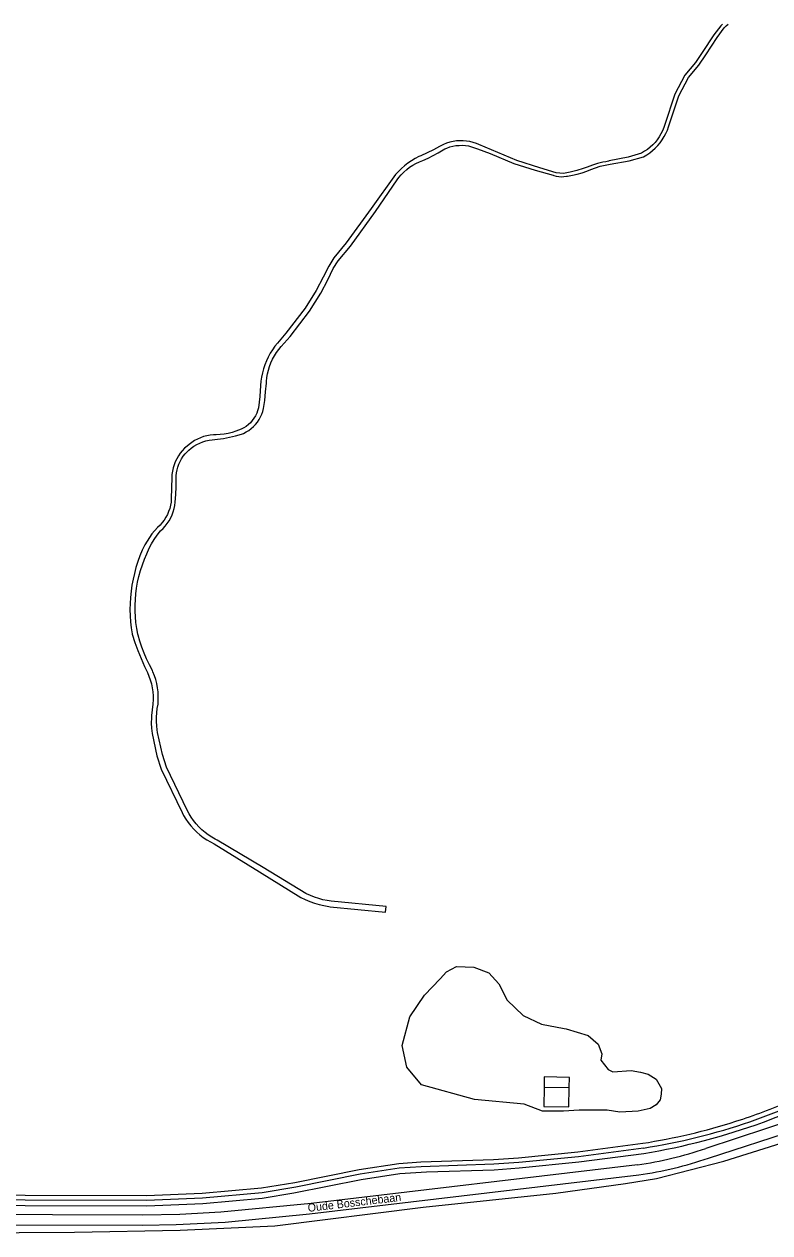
# Model space of a CAD drawing. Extents: x 137000 to 140001, y 403500 to 406000.
# Drawn here: x 138682.6 to 138915.5, y 405622.5 to 406000 of the extents above; entities that cross this region are included whole.
import ezdxf

# ---------------------------------------------------------------- set-up
doc = ezdxf.new("R2010")
doc.units = 0
for name, color, linetype in [('gg-anno-openbare ruimte label', 7, 'Continuous'), ('gg-bbg-luifel en loopbrug', 7, 'Continuous'), ('gg-bbg-overig bouwwerk', 7, 'Continuous'), ('gg-knt-bronhoudergrens', 7, 'Continuous'), ('gg-knt-verharding', 7, 'Continuous'), ('gt-grn-groengrens', 7, 'Continuous'), ('gt-grn-groengrens NZ', 7, 'Continuous'), ('gx-grn-maaiveld', 7, 'Continuous')]:
    doc.layers.add(name, color=color, linetype=linetype)

msp = doc.modelspace()

# ---------------------------------------------------------------- linework, layer by layer
at = {"layer": 'gg-bbg-luifel en loopbrug'}
msp.add_line((138845.02, 405668.06), (138852.87, 405667.93), dxfattribs=at)
msp.add_lwpolyline([(138852.87, 405667.93), (138852.92, 405671.08), (138845.08, 405671.21), (138845.02, 405668.06)], dxfattribs=at)
at = {"layer": 'gg-bbg-overig bouwwerk'}
msp.add_lwpolyline([(138845.02, 405668.06), (138844.92, 405662.04), (138852.76, 405661.91), (138852.87, 405667.93)], dxfattribs=at)
at = {"layer": 'gg-knt-bronhoudergrens'}
msp.add_lwpolyline([(138659.36, 405622.56), (138663.63, 405622.55), (138698.36, 405622.75), (138731.28, 405623.33), (138760.93, 405624.73), (138807.2, 405630.57), (138848.69, 405634.92), (138870.43, 405637.95), (138880.17, 405639.47), (138901.12, 405644.91), (138929.96, 405653.95), (138949.6, 405660.12), (138957.13, 405662.06), (138962.26, 405662.86), (138977.74, 405662.68)], dxfattribs=at)
at = {"layer": 'gg-knt-verharding'}
for p, q in [((138943.08, 405664.55), (138895.49, 405648.85)), ((138896.38, 405645.88), (138943.82, 405661.31))]:
    msp.add_line(p, q, dxfattribs=at)
for points in [[(138913.57, 405657.13), (138917.53, 405658.62), (138921.47, 405660.18), (138924.88, 405661.61), (138928.27, 405663.1), (138933.91, 405665.95)], [(138606.79, 405631.24), (138720.86, 405630.99), (138738.44, 405631.71), (138756.93, 405633.38), (138766.88, 405635.02), (138787.84, 405639.17), (138799.96, 405641.1), (138808.28, 405641.59), (138829.37, 405642.26), (138837.25, 405642.82), (138855.9, 405644.69), (138876.13, 405647.31)], [(138876.03, 405649.02), (138855.75, 405646.31), (138837.13, 405644.49), (138829.28, 405643.99), (138806.56, 405643.19), (138799.78, 405642.75), (138787.55, 405640.82), (138767.44, 405636.82), (138756.97, 405635.08), (138738.33, 405633.38), (138720.82, 405632.69), (138606.85, 405632.97)], [(138874.22, 405643.73), (138772.25, 405631.7), (138744, 405628.98), (138731.23, 405628.29), (138719.7, 405628.09), (138606.68, 405628.5)], [(138606.6, 405625.15), (138719.6, 405624.93), (138730.03, 405625.11), (138745.36, 405625.88), (138771.74, 405628.49), (138874.58, 405640.63)]]:
    msp.add_lwpolyline(points, dxfattribs=at)
for centre, radius, start, end in [((138846.5, 405839.73), 192.99, 288.9912, 293.1914), ((138846.57, 405839.6), 192.84, 278.7876, 288.984), ((138841.4, 405855.99), 211.55, 279.449, 289.9462), ((138853.13, 405778.11), 136.02, 278.9209, 288.1439), ((138857.67, 405758.77), 119.34, 278.1474, 288.9272)]:
    msp.add_arc(centre, radius, start, end, dxfattribs=at)
at = {"layer": 'gt-grn-groengrens'}
msp.add_lwpolyline([(138803.04, 405689.95), (138807.65, 405696.78), (138812.54, 405701.82), (138814.56, 405704.01), (138817.61, 405705.73), (138823.09, 405705.48), (138827.76, 405703.77), (138830.89, 405700.34), (138833.49, 405695.18), (138838.49, 405690.42), (138844.19, 405687.68), (138851.23, 405686.33), (138851.91, 405686.2), (138858.74, 405684.21), (138861.87, 405681.43), (138863.07, 405678.42), (138862.78, 405676.46), (138864.98, 405673.59), (138866.52, 405672.79), (138872.23, 405673.23), (138875.13, 405672.75), (138877.56, 405672.09), (138880.04, 405670.53), (138881.72, 405667.62), (138881.62, 405665.84), (138881.28, 405664.11), (138880.01, 405662.47), (138878.18, 405661.4), (138874.43, 405660.57), (138868.68, 405660.27), (138864.7, 405660.89), (138855.94, 405660.88), (138851.12, 405660.57), (138844.47, 405660.5), (138838.77, 405662.77), (138823.32, 405664.14), (138806.67, 405668.8), (138802.15, 405674.3), (138800.67, 405681.05), (138803.04, 405689.95)], dxfattribs=at)
for centre, radius, start, end in [((138846.4, 405840), 191.77, 287.7607, 293.1874), ((138846.54, 405839.73), 191.47, 278.7943, 287.7443)]:
    msp.add_arc(centre, radius, start, end, dxfattribs=at)
at = {"layer": 'gt-grn-groengrens NZ'}
msp.add_lwpolyline([(138606.84, 405634.47), (138720.79, 405634.19), (138738.23, 405634.88), (138756.78, 405636.57), (138767.17, 405638.3), (138787.29, 405642.3), (138799.62, 405644.24), (138806.49, 405644.69), (138829.21, 405645.49), (138837.01, 405645.99), (138855.58, 405647.8), (138875.82, 405650.51)], dxfattribs=at)
at = {"layer": 'gx-grn-maaiveld'}
msp.add_lwpolyline([(138900.74, 406000), (138900.2, 405999.46), (138898.02, 405996.68), (138894.42, 405991.2), (138892.3, 405987.99), (138888.99, 405984.1), (138885.9, 405978.11), (138882.61, 405968.34), (138882.4, 405967.71), (138881.99, 405966.71), (138881.52, 405965.74), (138880.97, 405964.81), (138880.36, 405963.93), (138879.68, 405963.09), (138878.95, 405962.3), (138878.15, 405961.57), (138877.31, 405960.9), (138876.42, 405960.29), (138875.48, 405959.76), (138871.28, 405958.45), (138865.31, 405957.27), (138865.09, 405957.23), (138864.25, 405957.06), (138863.41, 405956.89), (138861.74, 405956.46), (138860.1, 405955.96), (138858.49, 405955.39), (138857.2, 405954.95), (138855.19, 405954.33), (138853.16, 405953.79), (138851.11, 405953.32), (138849.95, 405953.46), (138848.78, 405953.6), (138843.65, 405955.16), (138836.54, 405957.44), (138824.65, 405962.46), (138823.88, 405962.77), (138822.87, 405963.09), (138821.84, 405963.34), (138820.79, 405963.51), (138819.74, 405963.6), (138818.68, 405963.6), (138817.62, 405963.53), (138816.57, 405963.38), (138815.54, 405963.15), (138814.53, 405962.85), (138813.54, 405962.46), (138812.3, 405961.75), (138810.41, 405960.73), (138808.48, 405959.78), (138806.52, 405958.91), (138805.91, 405958.63), (138804.73, 405958.03), (138803.58, 405957.36), (138802.48, 405956.62), (138801.43, 405955.81), (138800.43, 405954.95), (138799.48, 405954.02), (138798.59, 405953.04), (138791.04, 405942.42), (138783.23, 405931.69), (138779.32, 405927.01), (138777.72, 405924.46), (138775.98, 405920.95), (138773.85, 405916.83), (138770.35, 405911.29), (138764.37, 405903.5), (138761.68, 405900.39), (138760.91, 405899.43), (138760.14, 405898.35), (138759.43, 405897.22), (138758.8, 405896.06), (138758.24, 405894.86), (138757.75, 405893.63), (138757.33, 405892.37), (138756.99, 405891.09), (138756.74, 405889.79), (138756.55, 405888.47), (138756.45, 405887.15), (138756.16, 405883.7), (138755.79, 405880.22), (138755.77, 405880.15), (138755.53, 405879.29), (138755.22, 405878.47), (138754.83, 405877.67), (138754.37, 405876.92), (138753.85, 405876.21), (138753.26, 405875.55), (138752.62, 405874.94), (138751.92, 405874.4), (138751.18, 405873.92), (138750.4, 405873.51), (138749.58, 405873.17), (138748.74, 405872.91), (138747.54, 405872.53), (138746.31, 405872.22), (138745.07, 405872), (138743.82, 405871.85), (138742.56, 405871.79), (138741.73, 405871.79), (138740.69, 405871.67), (138739.66, 405871.48), (138738.65, 405871.21), (138737.67, 405870.86), (138736.71, 405870.43), (138735.8, 405869.94), (138734.92, 405869.38), (138734.08, 405868.75), (138733.47, 405868.22), (138732.71, 405867.54), (138731.99, 405866.8), (138731.34, 405866), (138730.76, 405865.16), (138730.24, 405864.28), (138729.79, 405863.36), (138729.41, 405862.4), (138729.11, 405861.42), (138728.89, 405860.42), (138728.74, 405859.4), (138728.69, 405858.56), (138728.55, 405851.77), (138728.46, 405850.76), (138728.29, 405849.77), (138728.05, 405848.79), (138727.72, 405847.83), (138727.32, 405846.9), (138726.85, 405846.01), (138726.31, 405845.15), (138725.7, 405844.34), (138725.03, 405843.59), (138724.27, 405842.86), (138722.5, 405840.85), (138720.29, 405837.43), (138719.48, 405835.7), (138718.75, 405833.94), (138718.1, 405832.15), (138717.52, 405830.34), (138717.01, 405828.5), (138716.59, 405826.64), (138716.24, 405824.77), (138715.97, 405822.88), (138715.78, 405820.99), (138715.67, 405819.08), (138715.64, 405817.18), (138715.69, 405815.27), (138715.82, 405813.37), (138716.03, 405811.48), (138716.32, 405809.6), (138716.34, 405809.49), (138717.2, 405806.94), (138718.13, 405804.41), (138719.13, 405801.91), (138720.21, 405799.45), (138721.09, 405797.58), (138721.57, 405796.42), (138721.98, 405795.22), (138722.32, 405794), (138722.58, 405792.76), (138722.75, 405791.51), (138722.85, 405790.25), (138722.87, 405788.99), (138722.81, 405787.73), (138722.8, 405787.66), (138722.34, 405784.12), (138722.32, 405783.39), (138722.31, 405781.74), (138722.39, 405780.1), (138722.55, 405778.46), (138724.07, 405771.52), (138725.37, 405767.32), (138731.9, 405753.78), (138732.39, 405752.88), (138733.08, 405751.75), (138733.84, 405750.67), (138734.67, 405749.63), (138735.55, 405748.65), (138736.5, 405747.72), (138737.49, 405746.84), (138738.54, 405746.03), (138739.64, 405745.29), (138740.77, 405744.61), (138741.95, 405744.01), (138756.11, 405735.3), (138768.99, 405727.29), (138770.38, 405726.63), (138771.8, 405726.04), (138773.26, 405725.53), (138774.73, 405725.09), (138776.23, 405724.73), (138777.74, 405724.45), (138778.22, 405724.38), (138795.48, 405722.73), (138795.67, 405724.5), (138778.54, 405726.12), (138777.21, 405726.31), (138775.89, 405726.58), (138774.59, 405726.92), (138773.3, 405727.34), (138772.05, 405727.84), (138770.83, 405728.4), (138770.56, 405728.54), (138757.22, 405736.63), (138742.85, 405745.18), (138742.29, 405745.47), (138741.17, 405746.11), (138740.1, 405746.82), (138739.08, 405747.59), (138738.1, 405748.43), (138737.18, 405749.32), (138736.32, 405750.27), (138735.52, 405751.28), (138734.78, 405752.33), (138734.11, 405753.42), (138733.5, 405754.56), (138727.03, 405767.97), (138725.79, 405771.97), (138724.29, 405778.84), (138724.17, 405779.58), (138724.01, 405780.92), (138723.93, 405782.27), (138723.93, 405783.62), (138724.01, 405784.97), (138724.17, 405786.32), (138724.41, 405787.65), (138724.49, 405788.93), (138724.49, 405790.22), (138724.41, 405791.51), (138724.25, 405792.79), (138724.01, 405794.06), (138723.69, 405795.31), (138723.3, 405796.54), (138722.83, 405797.74), (138722.63, 405798.2), (138721.71, 405799.95), (138720.85, 405801.75), (138720.07, 405803.57), (138719.36, 405805.43), (138718.73, 405807.31), (138718.17, 405809.22), (138718.08, 405809.54), (138717.76, 405811.32), (138717.51, 405813.12), (138717.35, 405814.92), (138717.26, 405816.73), (138717.25, 405818.54), (138717.33, 405820.34), (138717.48, 405822.15), (138717.7, 405823.87), (138718.04, 405825.71), (138718.45, 405827.54), (138718.94, 405829.35), (138719.51, 405831.13), (138720.16, 405832.89), (138720.88, 405834.62), (138721.67, 405836.32), (138722.39, 405837.73), (138723.24, 405839.11), (138724.16, 405840.44), (138725.14, 405841.73), (138725.21, 405841.81), (138725.97, 405842.52), (138726.67, 405843.27), (138727.3, 405844.08), (138727.88, 405844.94), (138728.38, 405845.84), (138728.81, 405846.77), (138729.17, 405847.74), (138729.45, 405848.72), (138729.66, 405849.73), (138729.78, 405850.71), (138729.97, 405853.12), (138730.07, 405855.54), (138730.1, 405857.98), (138730.1, 405858.92), (138730.18, 405859.86), (138730.34, 405860.79), (138730.58, 405861.7), (138730.9, 405862.59), (138731.29, 405863.45), (138731.75, 405864.28), (138732.27, 405865.06), (138732.87, 405865.79), (138733.52, 405866.48), (138734.02, 405866.93), (138734.8, 405867.58), (138735.64, 405868.17), (138736.52, 405868.69), (138737.43, 405869.15), (138738.38, 405869.52), (138739.36, 405869.83), (138740.35, 405870.05), (138741.36, 405870.2), (138742.19, 405870.27), (138743.01, 405870.36), (138744.89, 405870.63), (138746.75, 405870.98), (138748.6, 405871.41), (138750.43, 405871.91), (138751.14, 405872.21), (138751.98, 405872.64), (138752.78, 405873.13), (138753.53, 405873.7), (138754.23, 405874.32), (138754.88, 405875), (138755.47, 405875.74), (138755.99, 405876.52), (138756.44, 405877.35), (138756.83, 405878.2), (138757.13, 405879.09), (138757.37, 405880.01), (138757.72, 405882.49), (138758.02, 405885.16), (138758.24, 405887.85), (138758.28, 405888.43), (138758.4, 405889.63), (138758.61, 405890.82), (138758.89, 405891.99), (138759.25, 405893.14), (138759.69, 405894.26), (138760.2, 405895.36), (138760.78, 405896.41), (138761.43, 405897.43), (138762.14, 405898.4), (138762.92, 405899.32), (138765.64, 405902.47), (138771.69, 405910.36), (138775.27, 405916.01), (138777.44, 405920.2), (138779.15, 405923.66), (138780.65, 405926.05), (138784.52, 405930.68), (138792.37, 405941.47), (138799.09, 405951.42), (138799.62, 405952.11), (138800.38, 405953), (138801.2, 405953.83), (138802.08, 405954.6), (138803, 405955.31), (138803.98, 405955.95), (138804.99, 405956.53), (138806.04, 405957.04), (138807.13, 405957.47), (138808.77, 405958.18), (138810.39, 405958.96), (138811.96, 405959.81), (138813.5, 405960.74), (138813.95, 405961.03), (138814.63, 405961.32), (138815.56, 405961.65), (138816.51, 405961.9), (138817.48, 405962.07), (138818.46, 405962.16), (138819.44, 405962.17), (138820.42, 405962.11), (138821.4, 405961.96), (138822.35, 405961.73), (138823.29, 405961.43), (138824.2, 405961.05), (138828.2, 405959.59), (138835.57, 405956.44), (138842.21, 405954.39), (138847.83, 405952.83), (138848.02, 405952.77), (138848.79, 405952.55), (138849.58, 405952.42), (138850.38, 405952.36), (138851.19, 405952.38), (138851.98, 405952.49), (138852.31, 405952.54), (138853.85, 405952.82), (138855.37, 405953.18), (138856.86, 405953.62), (138858.33, 405954.14), (138859.58, 405954.65), (138861.06, 405955.17), (138862.56, 405955.61), (138864.08, 405955.98), (138865.62, 405956.26), (138871.63, 405957.29), (138876.09, 405958.61), (138877.07, 405959.18), (138878.02, 405959.82), (138878.91, 405960.52), (138879.76, 405961.29), (138880.54, 405962.11), (138881.27, 405962.98), (138881.94, 405963.91), (138882.54, 405964.87), (138883.07, 405965.88), (138883.53, 405966.92), (138883.88, 405967.91), (138887.14, 405977.59), (138890.12, 405983.34), (138893.39, 405987.18), (138895.55, 405990.45), (138899.11, 405995.89), (138901.24, 405998.88), (138901.88, 405999.49), (138902.51, 406000)], dxfattribs=at)

# ---------------------------------------------------------------- texts
at = {"layer": 'gg-anno-openbare ruimte label'}
msp.add_text('Oude Bosschebaan', height=2.5, rotation=6.7, dxfattribs=at).set_placement((138771.31, 405629.08))

doc.saveas('drawing.dxf')
